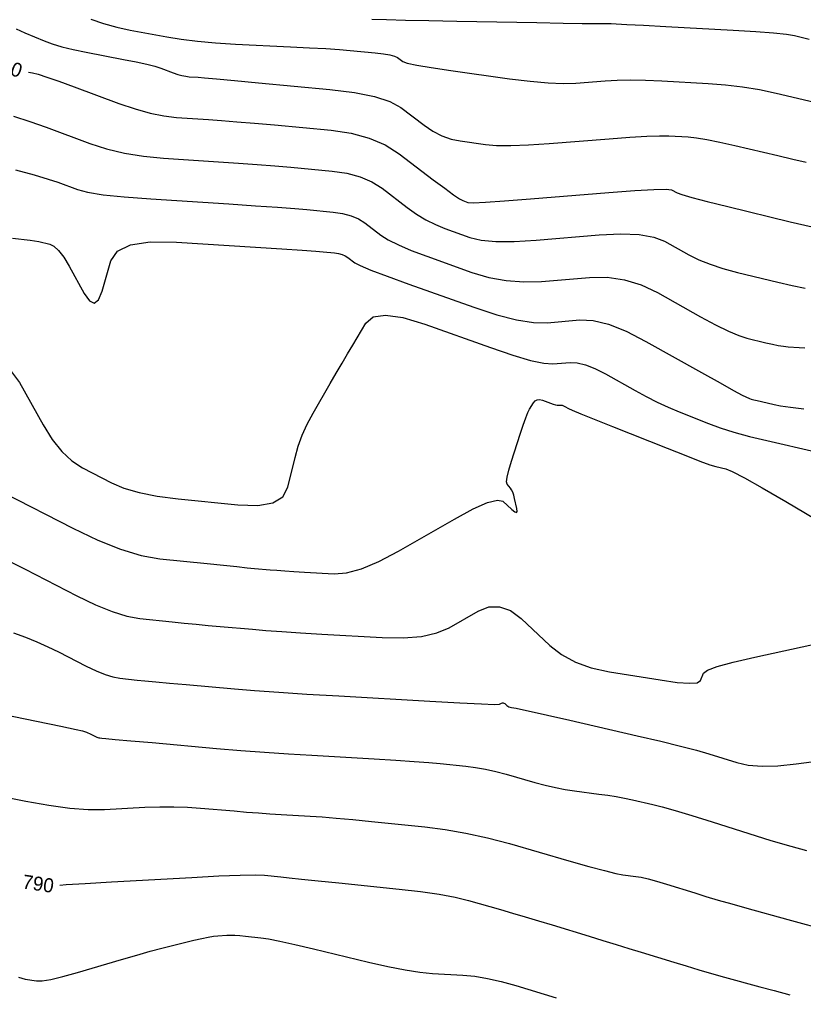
# Model space of a CAD drawing. Extents: x 2082232 to 2083549, y 592624 to 593832.
# Drawn here: x 2082327.71 to 2082366.85, y 593026.54 to 593075.08 of the extents above; entities that cross this region are included whole.
import ezdxf

# ---------------------------------------------------------------- set-up
doc = ezdxf.new("R2010")
doc.units = 0
doc.layers.add('DT_X_Contour_Major', color=7, linetype='Continuous')
doc.layers.add('DT_X_Contour_Minor', color=7, linetype='Continuous')

msp = doc.modelspace()

# ---------------------------------------------------------------- linework, layer by layer
at = {"layer": 'DT_X_Contour_Major'}
for points in [[(2082328.161, 593072.455), (2082328.363, 593072.416), (2082328.642, 593072.344), (2082329.08, 593072.204), (2082329.679, 593071.995), (2082330.438, 593071.718), (2082332.674, 593070.887), (2082333.482, 593070.61), (2082334.23, 593070.401), (2082334.918, 593070.26), (2082335.546, 593070.187), (2082337.141, 593070.084), (2082337.796, 593070.037), (2082338.565, 593069.976), (2082339.449, 593069.901), (2082340.448, 593069.81), (2082343.263, 593069.548), (2082344.267, 593069.402), (2082345.167, 593069.158), (2082345.964, 593068.816), (2082346.658, 593068.378), (2082348.369, 593067.079), (2082348.943, 593066.648), (2082349.38, 593066.331), (2082349.68, 593066.127), (2082349.844, 593066.036), (2082350.099, 593065.945), (2082350.366, 593065.93), (2082350.975, 593065.954), (2082351.927, 593066.017), (2082353.222, 593066.119), (2082357.131, 593066.442), (2082358.426, 593066.54), (2082359.38, 593066.595), (2082359.993, 593066.604), (2082360.265, 593066.57), (2082360.536, 593066.418), (2082360.77, 593066.333), (2082361.271, 593066.191), (2082362.037, 593065.992), (2082363.069, 593065.736), (2082366.177, 593064.979), (2082367.282, 593064.725)], [(2082326.926, 593051.451), (2082330.373, 593049.672), (2082331.614, 593049.076), (2082332.753, 593048.624), (2082333.79, 593048.317), (2082334.725, 593048.153), (2082337.081, 593047.908), (2082337.892, 593047.824), (2082338.555, 593047.757), (2082339.072, 593047.706), (2082339.441, 593047.672), (2082340.232, 593047.602), (2082340.561, 593047.575), (2082340.955, 593047.547), (2082341.414, 593047.517), (2082341.939, 593047.485), (2082343.425, 593047.399), (2082344.044, 593047.446), (2082344.784, 593047.651), (2082345.647, 593048.014), (2082346.632, 593048.535), (2082349.421, 593050.136), (2082350.357, 593050.642), (2082351.074, 593050.958), (2082351.571, 593051.085), (2082351.848, 593051.022), (2082352.296, 593050.603), (2082352.437, 593050.489), (2082352.526, 593050.46), (2082352.562, 593050.518), (2082352.545, 593050.662), (2082352.428, 593051.159), (2082352.383, 593051.331), (2082352.333, 593051.475), (2082352.279, 593051.59), (2082352.221, 593051.677), (2082352.06, 593051.869), (2082352.028, 593051.995), (2082352.052, 593052.229), (2082352.132, 593052.572), (2082352.268, 593053.022), (2082352.706, 593054.368), (2082352.858, 593054.824), (2082352.988, 593055.185), (2082353.094, 593055.449), (2082353.177, 593055.616), (2082353.369, 593055.935), (2082353.45, 593056.033), (2082353.552, 593056.087), (2082353.674, 593056.098), (2082353.816, 593056.065), (2082354.222, 593055.921), (2082354.36, 593055.874), (2082354.47, 593055.841), (2082354.552, 593055.823), (2082354.607, 593055.819), (2082354.714, 593055.828), (2082354.758, 593055.826), (2082354.809, 593055.814), (2082354.867, 593055.791), (2082354.933, 593055.757), (2082355.116, 593055.654), (2082355.305, 593055.57), (2082355.733, 593055.392), (2082356.401, 593055.121), (2082357.308, 593054.758), (2082360.046, 593053.666), (2082360.968, 593053.302), (2082361.68, 593053.03), (2082362.182, 593052.849), (2082362.473, 593052.76), (2082362.971, 593052.645), (2082363.297, 593052.51), (2082363.905, 593052.192), (2082364.793, 593051.691), (2082365.961, 593051.008), (2082369.451, 593048.94)], [(2082329.722, 593031.859), (2082330.037, 593031.879), (2082330.986, 593031.936), (2082332.304, 593032.012), (2082336.311, 593032.243), (2082337.664, 593032.315), (2082338.719, 593032.357), (2082339.476, 593032.369), (2082339.934, 593032.35), (2082340.758, 593032.262), (2082341.17, 593032.218), (2082341.789, 593032.155), (2082342.613, 593032.071), (2082343.645, 593031.966), (2082346.67, 593031.661), (2082347.737, 593031.539), (2082348.67, 593031.403), (2082349.467, 593031.253), (2082350.13, 593031.089), (2082351.719, 593030.633), (2082352.327, 593030.456), (2082352.959, 593030.27), (2082353.616, 593030.074), (2082354.298, 593029.867), (2082356.148, 593029.304), (2082356.831, 593029.095), (2082357.493, 593028.893), (2082358.133, 593028.696), (2082358.753, 593028.505), (2082360.376, 593028.005), (2082360.991, 593027.818), (2082361.619, 593027.632), (2082362.26, 593027.448), (2082362.914, 593027.265), (2082364.674, 593026.778), (2082365.379, 593026.588), (2082366.175, 593026.38)]]:
    msp.add_lwpolyline(points, dxfattribs=at)
at = {"layer": 'DT_X_Contour_Minor'}
for points in [[(2082331.27, 593075.092), (2082331.91, 593074.879), (2082332.567, 593074.7), (2082333.241, 593074.553), (2082335.063, 593074.207), (2082335.79, 593074.088), (2082336.603, 593073.988), (2082337.503, 593073.909), (2082338.489, 593073.849), (2082341.234, 593073.718), (2082342.193, 593073.669), (2082343.011, 593073.622), (2082343.687, 593073.577), (2082344.222, 593073.533), (2082345.46, 593073.418), (2082345.878, 593073.371), (2082346.205, 593073.316), (2082346.44, 593073.253), (2082346.583, 593073.183), (2082346.844, 593072.986), (2082347.067, 593072.902), (2082347.54, 593072.798), (2082348.265, 593072.674), (2082349.24, 593072.531), (2082352.176, 593072.122), (2082353.208, 593071.993), (2082354.102, 593071.914), (2082354.859, 593071.884), (2082355.479, 593071.903), (2082356.949, 593072.021), (2082357.54, 593072.053), (2082358.209, 593072.063), (2082358.957, 593072.049), (2082359.784, 593072.013), (2082362.095, 593071.885), (2082362.957, 593071.819), (2082363.808, 593071.716), (2082364.648, 593071.576), (2082365.478, 593071.4), (2082367.678, 593070.881)], [(2082345.306, 593075.096), (2082346.031, 593075.075), (2082346.978, 593075.052), (2082348.146, 593075.027), (2082349.536, 593075), (2082353.538, 593074.927), (2082354.855, 593074.903), (2082355.805, 593074.886), (2082356.388, 593074.876), (2082356.603, 593074.873), (2082356.687, 593074.875), (2082356.728, 593074.876), (2082356.788, 593074.876), (2082356.866, 593074.876), (2082356.963, 593074.875), (2082357.246, 593074.873), (2082357.496, 593074.863), (2082358.034, 593074.836), (2082358.861, 593074.793), (2082359.976, 593074.732), (2082363.333, 593074.546), (2082364.47, 593074.477), (2082365.36, 593074.409), (2082366.005, 593074.342), (2082366.404, 593074.276), (2082367.14, 593074.103)], [(2082327.542, 593074.612), (2082327.985, 593074.419), (2082328.939, 593074.01), (2082329.339, 593073.859), (2082329.823, 593073.713), (2082330.392, 593073.573), (2082331.046, 593073.439), (2082332.901, 593073.086), (2082333.539, 593072.96), (2082334.061, 593072.845), (2082334.468, 593072.741), (2082334.76, 593072.648), (2082335.384, 593072.416), (2082335.61, 593072.339), (2082335.819, 593072.281), (2082336.011, 593072.241), (2082336.186, 593072.221), (2082336.632, 593072.192), (2082336.945, 593072.167), (2082337.551, 593072.114), (2082338.449, 593072.032), (2082339.64, 593071.922), (2082343.206, 593071.59), (2082344.431, 593071.44), (2082345.43, 593071.239), (2082346.203, 593070.986), (2082346.75, 593070.682), (2082347.909, 593069.802), (2082348.348, 593069.505), (2082348.796, 593069.275), (2082349.253, 593069.11), (2082349.718, 593069.011), (2082350.971, 593068.837), (2082351.522, 593068.791), (2082352.238, 593068.784), (2082353.116, 593068.815), (2082354.158, 593068.886), (2082357.156, 593069.125), (2082358.184, 593069.201), (2082359.022, 593069.25), (2082359.668, 593069.271), (2082360.124, 593069.265), (2082361.085, 593069.212), (2082361.501, 593069.171), (2082362.028, 593069.087), (2082362.667, 593068.961), (2082363.416, 593068.792), (2082365.564, 593068.285), (2082366.32, 593068.107), (2082366.978, 593067.95)], [(2082327.408, 593070.258), (2082328.233, 593069.989), (2082329.05, 593069.697), (2082331.221, 593068.891), (2082332.062, 593068.618), (2082332.956, 593068.404), (2082333.904, 593068.249), (2082334.906, 593068.153), (2082337.65, 593067.975), (2082338.647, 593067.908), (2082339.58, 593067.839), (2082340.45, 593067.769), (2082341.255, 593067.698), (2082343.319, 593067.506), (2082344.055, 593067.399), (2082344.715, 593067.22), (2082345.3, 593066.97), (2082345.808, 593066.648), (2082347.063, 593065.696), (2082347.533, 593065.362), (2082348.004, 593065.076), (2082348.474, 593064.837), (2082348.944, 593064.646), (2082350.197, 593064.199), (2082350.756, 593064.065), (2082351.493, 593063.996), (2082352.407, 593063.995), (2082353.499, 593064.059), (2082356.647, 593064.319), (2082357.737, 593064.372), (2082358.645, 593064.338), (2082359.371, 593064.216), (2082359.916, 593064.005), (2082361.125, 593063.327), (2082361.617, 593063.082), (2082362.185, 593062.853), (2082362.829, 593062.643), (2082363.548, 593062.449), (2082365.57, 593061.956), (2082366.289, 593061.791), (2082366.93, 593061.666)], [(2082327.511, 593067.566), (2082328.44, 593067.314), (2082329.145, 593067.108), (2082329.626, 593066.948), (2082330.609, 593066.583), (2082331.114, 593066.451), (2082331.892, 593066.33), (2082332.943, 593066.219), (2082334.266, 593066.119), (2082338.159, 593065.867), (2082339.498, 593065.778), (2082340.595, 593065.702), (2082341.45, 593065.638), (2082342.063, 593065.586), (2082343.376, 593065.464), (2082343.844, 593065.396), (2082344.264, 593065.282), (2082344.635, 593065.123), (2082344.958, 593064.918), (2082345.756, 593064.313), (2082346.124, 593064.076), (2082346.628, 593063.821), (2082347.268, 593063.548), (2082348.044, 593063.256), (2082350.296, 593062.453), (2082351.147, 593062.199), (2082352.01, 593062.039), (2082352.887, 593061.972), (2082353.776, 593061.999), (2082356.164, 593062.196), (2082357.048, 593062.204), (2082357.91, 593062.081), (2082358.75, 593061.827), (2082359.567, 593061.441), (2082361.715, 593060.236), (2082362.464, 593059.83), (2082363.099, 593059.516), (2082363.62, 593059.293), (2082364.028, 593059.162), (2082364.963, 593058.934), (2082365.296, 593058.858), (2082365.593, 593058.8), (2082365.853, 593058.76), (2082366.078, 593058.74), (2082366.629, 593058.708), (2082366.912, 593058.686)], [(2082327.354, 593064.158), (2082328.243, 593064.053), (2082328.675, 593063.988), (2082329.218, 593063.865), (2082329.431, 593063.761), (2082329.664, 593063.541), (2082329.916, 593063.206), (2082330.188, 593062.755), (2082330.939, 593061.399), (2082331.206, 593061.025), (2082331.443, 593060.919), (2082331.652, 593061.082), (2082331.831, 593061.513), (2082332.269, 593063.021), (2082332.598, 593063.504), (2082333.255, 593063.821), (2082334.24, 593063.974), (2082335.554, 593063.96), (2082339.494, 593063.705), (2082340.814, 593063.619), (2082341.816, 593063.552), (2082342.502, 593063.503), (2082342.871, 593063.474), (2082343.432, 593063.422), (2082343.632, 593063.393), (2082343.812, 593063.344), (2082343.971, 593063.276), (2082344.109, 593063.189), (2082344.45, 593062.93), (2082344.714, 593062.79), (2082345.252, 593062.567), (2082346.061, 593062.259), (2082347.144, 593061.866), (2082350.394, 593060.707), (2082351.537, 593060.333), (2082352.528, 593060.081), (2082353.366, 593059.949), (2082354.053, 593059.939), (2082355.681, 593060.073), (2082356.345, 593060.044), (2082357.117, 593059.857), (2082357.997, 593059.511), (2082358.985, 593059.006), (2082361.762, 593057.45), (2082362.682, 593056.935), (2082363.357, 593056.561), (2082363.79, 593056.325), (2082363.978, 593056.229), (2082364.156, 593056.158), (2082364.243, 593056.128), (2082364.372, 593056.091), (2082364.544, 593056.047), (2082364.757, 593055.996), (2082365.38, 593055.851), (2082365.701, 593055.791), (2082366.195, 593055.717), (2082366.864, 593055.63)], [(2082327.159, 593057.686), (2082327.717, 593056.953), (2082328.888, 593054.84), (2082329.34, 593054.111), (2082329.819, 593053.51), (2082330.324, 593053.037), (2082330.855, 593052.692), (2082332.308, 593051.942), (2082332.924, 593051.681), (2082333.684, 593051.462), (2082334.587, 593051.284), (2082335.632, 593051.147), (2082338.612, 593050.837), (2082339.607, 593050.805), (2082340.355, 593050.942), (2082340.857, 593051.247), (2082341.112, 593051.721), (2082341.466, 593053.211), (2082341.621, 593053.768), (2082341.823, 593054.324), (2082342.072, 593054.877), (2082342.367, 593055.428), (2082343.214, 593056.894), (2082343.524, 593057.426), (2082343.815, 593057.924), (2082344.089, 593058.388), (2082344.345, 593058.818), (2082345.005, 593059.917), (2082345.375, 593060.223), (2082345.99, 593060.317), (2082346.849, 593060.198), (2082347.954, 593059.867), (2082351.225, 593058.7), (2082352.339, 593058.321), (2082353.228, 593058.057), (2082353.892, 593057.91), (2082354.33, 593057.879), (2082355.198, 593057.951), (2082355.552, 593057.935), (2082355.963, 593057.835), (2082356.432, 593057.651), (2082356.959, 593057.382), (2082358.439, 593056.552), (2082358.993, 593056.252), (2082359.545, 593055.976), (2082360.095, 593055.723), (2082360.643, 593055.493), (2082362.101, 593054.912), (2082362.694, 593054.695), (2082363.378, 593054.479), (2082364.155, 593054.264), (2082365.023, 593054.051), (2082367.461, 593053.485)], [(2082327.064, 593048.097), (2082327.99, 593047.632), (2082330.577, 593046.296), (2082331.502, 593045.85), (2082332.334, 593045.514), (2082333.075, 593045.286), (2082333.723, 593045.169), (2082335.33, 593045.002), (2082335.932, 593044.94), (2082336.534, 593044.881), (2082337.135, 593044.825), (2082337.736, 593044.771), (2082339.338, 593044.63), (2082340.005, 593044.575), (2082340.804, 593044.518), (2082341.735, 593044.457), (2082342.799, 593044.393), (2082345.811, 593044.219), (2082346.867, 593044.2), (2082347.776, 593044.276), (2082348.539, 593044.446), (2082349.155, 593044.71), (2082350.601, 593045.541), (2082351.142, 593045.75), (2082351.682, 593045.757), (2082352.22, 593045.56), (2082352.756, 593045.16), (2082354.183, 593043.822), (2082354.77, 593043.364), (2082355.462, 593042.993), (2082356.258, 593042.708), (2082357.158, 593042.51), (2082359.698, 593042.098), (2082360.538, 593041.98), (2082361.153, 593041.935), (2082361.543, 593041.963), (2082361.708, 593042.064), (2082361.85, 593042.43), (2082362.05, 593042.583), (2082362.545, 593042.77), (2082363.336, 593042.988), (2082364.421, 593043.24), (2082367.707, 593043.953)], [(2082327.408, 593044.455), (2082328.006, 593044.238), (2082328.581, 593044.006), (2082329.133, 593043.759), (2082329.663, 593043.499), (2082331.043, 593042.787), (2082331.536, 593042.548), (2082331.98, 593042.369), (2082332.375, 593042.248), (2082332.721, 593042.185), (2082333.578, 593042.096), (2082333.973, 593042.057), (2082334.513, 593042.006), (2082335.199, 593041.944), (2082336.031, 593041.87), (2082338.444, 593041.657), (2082339.449, 593041.575), (2082340.653, 593041.488), (2082342.056, 593041.397), (2082343.658, 593041.301), (2082348.196, 593041.038), (2082349.69, 593040.954), (2082350.768, 593040.901), (2082351.431, 593040.878), (2082351.677, 593040.885), (2082351.781, 593040.945), (2082351.82, 593040.96), (2082351.859, 593040.96), (2082351.897, 593040.946), (2082351.935, 593040.918), (2082352.038, 593040.822), (2082352.082, 593040.789), (2082352.137, 593040.761), (2082352.203, 593040.739), (2082352.279, 593040.723), (2082352.499, 593040.687), (2082352.729, 593040.64), (2082353.254, 593040.523), (2082354.074, 593040.338), (2082355.188, 593040.084), (2082358.552, 593039.315), (2082359.722, 593039.042), (2082360.706, 593038.8), (2082361.506, 593038.589), (2082362.121, 593038.409), (2082363.515, 593037.97), (2082364.093, 593037.843), (2082364.779, 593037.789), (2082365.574, 593037.809), (2082366.478, 593037.903), (2082369.035, 593038.252)], [(2082326.868, 593040.395), (2082328.552, 593040.048), (2082329.777, 593039.793), (2082330.542, 593039.629), (2082330.848, 593039.557), (2082331.052, 593039.486), (2082331.127, 593039.459), (2082331.2, 593039.43), (2082331.269, 593039.399), (2082331.335, 593039.366), (2082331.509, 593039.277), (2082331.57, 593039.247), (2082331.626, 593039.224), (2082331.676, 593039.209), (2082331.719, 593039.201), (2082331.827, 593039.19), (2082332.013, 593039.173), (2082332.492, 593039.13), (2082333.263, 593039.062), (2082334.326, 593038.969), (2082337.551, 593038.684), (2082338.755, 593038.583), (2082339.949, 593038.491), (2082341.133, 593038.409), (2082342.306, 593038.336), (2082345.421, 593038.156), (2082346.503, 593038.091), (2082347.413, 593038.03), (2082348.15, 593037.975), (2082348.714, 593037.924), (2082349.99, 593037.795), (2082350.475, 593037.734), (2082350.974, 593037.646), (2082351.487, 593037.532), (2082352.014, 593037.392), (2082353.437, 593036.982), (2082353.962, 593036.841), (2082354.466, 593036.723), (2082354.951, 593036.629), (2082355.416, 593036.559), (2082356.631, 593036.403), (2082357.078, 593036.341), (2082357.506, 593036.272), (2082357.915, 593036.196), (2082358.306, 593036.112), (2082359.324, 593035.879), (2082359.795, 593035.76), (2082360.446, 593035.575), (2082361.276, 593035.327), (2082362.285, 593035.013), (2082365.216, 593034.091), (2082366.212, 593033.793), (2082367.003, 593033.591)], [(2082324.801, 593036.692), (2082328.025, 593036.047), (2082329.177, 593035.84), (2082330.216, 593035.703), (2082331.143, 593035.636), (2082331.955, 593035.639), (2082333.972, 593035.74), (2082334.713, 593035.766), (2082335.422, 593035.769), (2082336.099, 593035.748), (2082336.745, 593035.704), (2082338.425, 593035.556), (2082339.044, 593035.504), (2082339.641, 593035.457), (2082340.216, 593035.417), (2082340.769, 593035.382), (2082342.214, 593035.299), (2082342.813, 593035.259), (2082343.526, 593035.201), (2082344.352, 593035.127), (2082345.292, 593035.035), (2082347.949, 593034.766), (2082348.96, 593034.638), (2082350, 593034.456), (2082351.069, 593034.218), (2082352.167, 593033.926), (2082355.134, 593033.073), (2082356.137, 593032.789), (2082356.922, 593032.578), (2082357.488, 593032.439), (2082357.836, 593032.372), (2082358.472, 593032.291), (2082358.746, 593032.244), (2082359.094, 593032.163), (2082359.514, 593032.049), (2082360.007, 593031.901), (2082361.418, 593031.463), (2082361.977, 593031.293), (2082362.597, 593031.11), (2082363.277, 593030.916), (2082364.017, 593030.709), (2082366.071, 593030.141), (2082366.793, 593029.943), (2082367.417, 593029.775)], [(2082327.659, 593027.253), (2082327.997, 593027.167), (2082328.555, 593027.077), (2082328.84, 593027.078), (2082329.278, 593027.148), (2082329.869, 593027.287), (2082330.612, 593027.494), (2082332.796, 593028.139), (2082333.566, 593028.363), (2082334.237, 593028.553), (2082334.81, 593028.708), (2082335.283, 593028.828), (2082336.414, 593029.102), (2082336.807, 593029.193), (2082337.136, 593029.261), (2082337.403, 593029.305), (2082337.606, 593029.327), (2082338.064, 593029.353), (2082338.25, 593029.358), (2082338.466, 593029.353), (2082338.712, 593029.337), (2082338.987, 593029.311), (2082339.759, 593029.228), (2082340.141, 593029.17), (2082340.708, 593029.057), (2082341.459, 593028.89), (2082342.394, 593028.669), (2082345.134, 593028.007), (2082346.104, 593027.786), (2082346.961, 593027.619), (2082347.702, 593027.505), (2082348.33, 593027.446), (2082349.85, 593027.36), (2082350.443, 593027.303), (2082351.081, 593027.197), (2082351.765, 593027.042), (2082352.493, 593026.837), (2082354.497, 593026.227)]]:
    msp.add_lwpolyline(points, dxfattribs=at)

# ---------------------------------------------------------------- texts
at = {"layer": 'DT_X_Contour_Major'}
for s, rotation, p in [('800', 340.8102, (2082326.219, 593072.668)), ('790', 351.471, (2082327.822, 593031.696))]:
    msp.add_text(s, height=0.7, rotation=rotation, dxfattribs=at).set_placement(p)

doc.saveas('drawing.dxf')
